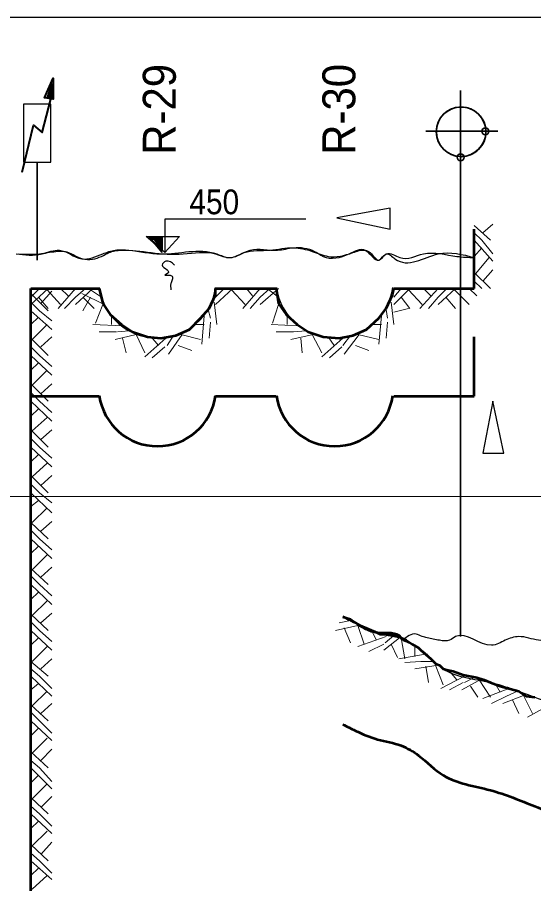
# Model space of a CAD drawing. Extents: x 8426.2 to 8495.4, y 19933.5 to 19963.2.
# Drawn here: x 8478.14 to 8482.31, y 19949.42 to 19956.41 of the extents above; entities that cross this region are included whole.
import ezdxf

# ---------------------------------------------------------------- set-up
doc = ezdxf.new("R2010")
doc.units = 0
doc.header["$LTSCALE"] = 0.11
doc.header["$PDMODE"] = 32
doc.header["$PDSIZE"] = 0.055
for name, color, linetype, lineweight in [('1', 7, 'Continuous', 35), ('2', 7, 'Continuous', 13), ('3', 7, 'Continuous', 25)]:
    doc.layers.add(name, color=color, linetype=linetype, lineweight=lineweight)

msp = doc.modelspace()

# ---------------------------------------------------------------- linework, layer by layer
at = {"layer": '1'}
for p, q in [((8481.72, 19955.08), (8481.72, 19955.82)), ((8481.44, 19955.49), (8482.01, 19955.49)), ((8481.45, 19955.49), (8482.02, 19955.49))]:
    msp.add_line(p, q, dxfattribs=at)
at = {"layer": '1', "lineweight": 40}
for points in [[(8478.43, 19955.75), (8478.36, 19955.76), (8478.43, 19955.92), (8478.43, 19955.75), (8478.42, 19955.76), (8478.42, 19955.87), (8478.38, 19955.76), (8478.42, 19955.76), (8478.42, 19955.82), (8478.39, 19955.77), (8478.41, 19955.77), (8478.42, 19955.8)], [(8478.18, 19955.16), (8478.27, 19955.54), (8478.34, 19955.48), (8478.41, 19955.75)]]:
    msp.add_lwpolyline(points, dxfattribs=at)
at = {"layer": '1'}
for points in [[(8481.72, 19951.41), (8481.72, 19953.26), (8481.72, 19955.82)], [(8481.92, 19955.49), (8481.72, 19955.49), (8481.72, 19955.69)], [(8481.52, 19955.49), (8481.72, 19955.49), (8481.72, 19955.28)], [(8479.31, 19954.51), (8479.21, 19954.63), (8479.31, 19954.63), (8479.31, 19954.53), (8479.22, 19954.62), (8479.3, 19954.62), (8479.3, 19954.55), (8479.25, 19954.61), (8479.29, 19954.61), (8479.3, 19954.56), (8479.28, 19954.61)], [(8479.29, 19954.58), (8479.28, 19954.61), (8479.27, 19954.61), (8479.3, 19954.56)]]:
    msp.add_lwpolyline(points, dxfattribs=at)
at = {"layer": '1', "lineweight": 25}
msp.add_lwpolyline([(8478.41, 19955.71), (8478.19, 19955.71), (8478.19, 19955.24), (8478.41, 19955.24)], close=True, dxfattribs=at)
msp.add_lwpolyline([(8480.47, 19954.78), (8479.33, 19954.78), (8479.33, 19954.51), (8479.18, 19954.64), (8479.45, 19954.64), (8479.33, 19954.51)], dxfattribs=at)
at = {"layer": '1'}
msp.add_circle((8481.7233, 19955.4865), 0.2004, dxfattribs=at)
for start, end in [(91.69169, 178.65388), (0.23992, 91.32093), (179.21012, 269.1404), (269.1404, 0.20975)]:
    msp.add_arc((8481.7245, 19955.4855), 0.2004, start, end, dxfattribs=at)
at = {"layer": '1', "lineweight": 25}
msp.add_spline([(8479.41, 19954.41), (8479.34, 19954.44), (8479.31, 19954.41), (8479.35, 19954.37), (8479.36, 19954.35), (8479.33, 19954.33), (8479.39, 19954.32), (8479.39, 19954.29), (8479.38, 19954.26), (8479.38, 19954.21)], degree=3, dxfattribs=at)
at = {"layer": '1'}
for p in [(8481.92, 19955.49), (8481.72, 19955.28)]:
    msp.add_point(p, dxfattribs=at)
at = {"layer": '2', "lineweight": 35}
msp.add_line((8478.3, 19955.24), (8478.3, 19954.45), dxfattribs=at)
at = {"layer": '2'}
for p, q in [((8481.83, 19954.73), (8481.96, 19954.61)), ((8481.9, 19954.67), (8481.98, 19954.74)), ((8481.83, 19954.67), (8481.89, 19954.61)), ((8481.83, 19954.61), (8481.98, 19954.44)), ((8481.89, 19954.61), (8481.98, 19954.5)), ((8481.83, 19954.48), (8481.89, 19954.55)), ((8481.84, 19954.34), (8481.95, 19954.47)), ((8481.9, 19954.28), (8481.98, 19954.37)), ((8481.83, 19954.35), (8481.96, 19954.22)), ((8478.32, 19954.22), (8478.25, 19954.15)), ((8478.39, 19954.22), (8478.25, 19954.09)), ((8478.61, 19954.22), (8478.47, 19954.06)), ((8478.49, 19954.22), (8478.55, 19954.16)), ((8478.69, 19954.22), (8478.61, 19954.15)), ((8478.75, 19954.22), (8478.61, 19954.09)), ((8479.81, 19954.22), (8479.74, 19954.15)), ((8479.88, 19954.22), (8479.74, 19954.09)), ((8480.1, 19954.22), (8479.96, 19954.06)), ((8479.99, 19954.22), (8480.04, 19954.16)), ((8480.18, 19954.22), (8480.1, 19954.15)), ((8480.25, 19954.22), (8480.1, 19954.09)), ((8481.24, 19954.22), (8481.18, 19954.15)), ((8481.31, 19954.22), (8481.18, 19954.09)), ((8481.54, 19954.22), (8481.39, 19954.06)), ((8481.42, 19954.22), (8481.48, 19954.16)), ((8481.61, 19954.22), (8481.54, 19954.15)), ((8481.68, 19954.22), (8481.54, 19954.09)), ((8481.79, 19954.22), (8481.85, 19954.16)), ((8481.83, 19954.28), (8481.89, 19954.22)), ((8478.25, 19954.18), (8478.39, 19954.04)), ((8478.31, 19954.15), (8478.39, 19954.06)), ((8478.33, 19954.1), (8478.42, 19954.2)), ((8478.38, 19954.21), (8478.49, 19954.09)), ((8478.61, 19954.15), (8478.52, 19954.06)), ((8478.84, 19954.09), (8478.66, 19954.18)), ((8478.73, 19954.15), (8478.67, 19954.04)), ((8478.67, 19954.15), (8478.76, 19954.06)), ((8478.82, 19954.15), (8478.73, 19954.21)), ((8479.87, 19954.21), (8479.98, 19954.09)), ((8480.1, 19954.15), (8480.02, 19954.06)), ((8480.25, 19954.15), (8480.17, 19954.21)), ((8481.24, 19954.15), (8481.31, 19954.06)), ((8481.3, 19954.21), (8481.41, 19954.09)), ((8481.54, 19954.15), (8481.46, 19954.06)), ((8481.6, 19954.15), (8481.68, 19954.06)), ((8481.67, 19954.21), (8481.79, 19954.09)), ((8478.25, 19954.11), (8478.32, 19954.04)), ((8478.83, 19954.09), (8478.77, 19953.94)), ((8479.73, 19954.11), (8479.75, 19953.93)), ((8480.25, 19954.09), (8480.2, 19953.94)), ((8481.16, 19954.11), (8481.18, 19953.93)), ((8478.25, 19954.04), (8478.42, 19953.89)), ((8478.32, 19954.04), (8478.42, 19953.96)), ((8479.68, 19954.05), (8479.7, 19953.98)), ((8481.12, 19954.05), (8481.13, 19953.98)), ((8481.18, 19954.03), (8481.3, 19954.06)), ((8478.25, 19953.93), (8478.31, 19953.99)), ((8478.9, 19954), (8478.9, 19953.93)), ((8479.65, 19954), (8479.63, 19953.77)), ((8479.7, 19953.95), (8479.69, 19953.82)), ((8480.32, 19954), (8480.32, 19953.93)), ((8481.08, 19954), (8481.06, 19953.77)), ((8481.13, 19953.95), (8481.12, 19953.82)), ((8478.26, 19953.81), (8478.38, 19953.93)), ((8478.99, 19953.92), (8478.75, 19953.93)), ((8478.94, 19953.87), (8478.8, 19953.87)), ((8479.04, 19953.88), (8478.95, 19953.87)), ((8479.57, 19953.93), (8479.65, 19953.93)), ((8480.41, 19953.92), (8480.19, 19953.93)), ((8480.37, 19953.87), (8480.23, 19953.87)), ((8480.47, 19953.88), (8480.37, 19953.87)), ((8481, 19953.93), (8481.08, 19953.93)), ((8478.25, 19953.82), (8478.39, 19953.68)), ((8478.33, 19953.75), (8478.42, 19953.83)), ((8479.1, 19953.85), (8478.93, 19953.81)), ((8478.99, 19953.82), (8479.02, 19953.7)), ((8479.1, 19953.85), (8479.17, 19953.7)), ((8479.34, 19953.82), (8479.17, 19953.67)), ((8479.22, 19953.83), (8479.28, 19953.76)), ((8479.4, 19953.84), (8479.35, 19953.76)), ((8479.47, 19953.85), (8479.36, 19953.69)), ((8479.46, 19953.85), (8479.62, 19953.81)), ((8480.53, 19953.85), (8480.35, 19953.81)), ((8480.43, 19953.82), (8480.44, 19953.7)), ((8480.52, 19953.85), (8480.6, 19953.7)), ((8480.77, 19953.82), (8480.6, 19953.67)), ((8480.65, 19953.83), (8480.7, 19953.76)), ((8480.83, 19953.84), (8480.77, 19953.76)), ((8480.9, 19953.85), (8480.78, 19953.69)), ((8480.89, 19953.85), (8481.06, 19953.81)), ((8478.25, 19953.75), (8478.32, 19953.68)), ((8479.33, 19953.75), (8479.23, 19953.66)), ((8479.44, 19953.76), (8479.55, 19953.72)), ((8480.76, 19953.75), (8480.66, 19953.66)), ((8480.87, 19953.76), (8480.98, 19953.72)), ((8478.25, 19953.68), (8478.42, 19953.52)), ((8478.32, 19953.68), (8478.42, 19953.59)), ((8478.25, 19953.56), (8478.31, 19953.62)), ((8478.26, 19953.44), (8478.38, 19953.56)), ((8478.25, 19953.45), (8478.39, 19953.31)), ((8478.33, 19953.37), (8478.42, 19953.45)), ((8478.25, 19953.38), (8478.32, 19953.31)), ((8478.25, 19953.31), (8478.42, 19953.15)), ((8478.32, 19953.31), (8478.42, 19953.22)), ((8478.25, 19953.19), (8478.31, 19953.25)), ((8478.26, 19953.07), (8478.38, 19953.18)), ((8478.25, 19953.08), (8478.39, 19952.94)), ((8478.33, 19953), (8478.42, 19953.08)), ((8478.25, 19953.01), (8478.32, 19952.94)), ((8478.25, 19952.94), (8478.42, 19952.78)), ((8478.32, 19952.94), (8478.42, 19952.85)), ((8478.25, 19952.82), (8478.31, 19952.88)), ((8478.26, 19952.7), (8478.38, 19952.81)), ((8478.25, 19952.71), (8478.39, 19952.57)), ((8478.33, 19952.63), (8478.42, 19952.71)), ((8478.25, 19952.64), (8478.32, 19952.57)), ((8478.25, 19952.57), (8478.42, 19952.41)), ((8478.32, 19952.57), (8478.42, 19952.49)), ((8478.25, 19952.46), (8478.31, 19952.51)), ((8478.26, 19952.33), (8478.38, 19952.45)), ((8478.25, 19952.33), (8478.39, 19952.2)), ((8478.33, 19952.26), (8478.42, 19952.34)), ((8478.25, 19952.27), (8478.32, 19952.2)), ((8478.25, 19952.2), (8478.42, 19952.04)), ((8478.32, 19952.2), (8478.42, 19952.11)), ((8478.25, 19952.08), (8478.31, 19952.14)), ((8478.26, 19951.95), (8478.38, 19952.07)), ((8478.25, 19951.96), (8478.39, 19951.83)), ((8478.33, 19951.89), (8478.42, 19951.97)), ((8478.25, 19951.9), (8478.32, 19951.83)), ((8478.25, 19951.83), (8478.42, 19951.67)), ((8478.25, 19951.71), (8478.31, 19951.77)), ((8478.32, 19951.83), (8478.42, 19951.74)), ((8478.26, 19951.58), (8478.38, 19951.7)), ((8478.25, 19951.59), (8478.39, 19951.46)), ((8478.33, 19951.52), (8478.42, 19951.6)), ((8478.25, 19951.53), (8478.32, 19951.46)), ((8480.89, 19951.5), (8480.71, 19951.46)), ((8480.83, 19951.54), (8480.74, 19951.52)), ((8480.89, 19951.5), (8480.94, 19951.35)), ((8478.25, 19951.46), (8478.42, 19951.3)), ((8478.32, 19951.46), (8478.42, 19951.37)), ((8480.78, 19951.48), (8480.83, 19951.36)), ((8481, 19951.46), (8481.04, 19951.38)), ((8481.18, 19951.42), (8481.11, 19951.36)), ((8478.25, 19951.34), (8478.31, 19951.4)), ((8481.12, 19951.41), (8480.89, 19951.33)), ((8481.1, 19951.35), (8480.98, 19951.29)), ((8481.24, 19951.41), (8481.1, 19951.3)), ((8481.16, 19951.35), (8481.21, 19951.24)), ((8481.24, 19951.4), (8481.27, 19951.23)), ((8478.26, 19951.21), (8478.38, 19951.33)), ((8481.35, 19951.34), (8481.35, 19951.25)), ((8478.25, 19951.21), (8478.39, 19951.09)), ((8478.33, 19951.15), (8478.42, 19951.23)), ((8481.45, 19951.27), (8481.22, 19951.23)), ((8481.4, 19951.21), (8481.27, 19951.2)), ((8481.5, 19951.21), (8481.4, 19951.21)), ((8478.25, 19951.15), (8478.32, 19951.09)), ((8481.54, 19951.18), (8481.35, 19951.15)), ((8481.44, 19951.17), (8481.46, 19951.04)), ((8481.52, 19951.17), (8481.58, 19951.02)), ((8478.25, 19951.09), (8478.42, 19950.93)), ((8478.32, 19951.09), (8478.42, 19950.99)), ((8481.75, 19951.09), (8481.56, 19950.99)), ((8481.63, 19951.13), (8481.69, 19951.06)), ((8481.89, 19951.07), (8481.73, 19950.98)), ((8481.83, 19951.08), (8481.75, 19951.04)), ((8478.25, 19950.98), (8478.31, 19951.03)), ((8481.74, 19951.04), (8481.63, 19950.98)), ((8481.8, 19951.01), (8481.86, 19950.92)), ((8481.87, 19951.06), (8481.96, 19950.92)), ((8482, 19951.03), (8482.04, 19950.96)), ((8478.26, 19950.85), (8478.38, 19950.97)), ((8482.11, 19950.99), (8481.9, 19950.91)), ((8482.09, 19950.93), (8481.97, 19950.87)), ((8482.24, 19950.94), (8482.06, 19950.87)), ((8482.18, 19950.97), (8482.09, 19950.93)), ((8482.23, 19950.93), (8482.3, 19950.79)), ((8478.25, 19950.86), (8478.39, 19950.73)), ((8478.33, 19950.79), (8478.42, 19950.87)), ((8482.14, 19950.9), (8482.19, 19950.79)), ((8482.46, 19950.87), (8482.26, 19950.76)), ((8478.25, 19950.8), (8478.32, 19950.73)), ((8478.25, 19950.73), (8478.42, 19950.57)), ((8478.32, 19950.73), (8478.42, 19950.63)), ((8478.25, 19950.61), (8478.31, 19950.67)), ((8478.26, 19950.47), (8478.38, 19950.59)), ((8478.25, 19950.48), (8478.39, 19950.35)), ((8478.33, 19950.41), (8478.42, 19950.5)), ((8478.25, 19950.41), (8478.32, 19950.35)), ((8478.25, 19950.35), (8478.42, 19950.18)), ((8478.32, 19950.35), (8478.42, 19950.24)), ((8478.25, 19950.23), (8478.31, 19950.29)), ((8478.26, 19950.1), (8478.38, 19950.22)), ((8478.25, 19950.11), (8478.39, 19949.98)), ((8478.33, 19950.03), (8478.42, 19950.12)), ((8478.25, 19950.04), (8478.32, 19949.98)), ((8478.25, 19949.98), (8478.42, 19949.82)), ((8478.32, 19949.98), (8478.42, 19949.88)), ((8478.25, 19949.86), (8478.31, 19949.92)), ((8478.26, 19949.72), (8478.38, 19949.84)), ((8478.33, 19949.65), (8478.42, 19949.75)), ((8478.25, 19949.73), (8478.39, 19949.6)), ((8478.25, 19949.66), (8478.32, 19949.6)), ((8478.25, 19949.6), (8478.42, 19949.45)), ((8478.25, 19949.48), (8478.31, 19949.54)), ((8478.32, 19949.6), (8478.42, 19949.5)), ((8478.26, 19949.37), (8478.38, 19949.48))]:
    msp.add_line(p, q, dxfattribs=at)
at = {"layer": '2', "lineweight": 53}
for p, q in [((8481.83, 19954.22), (8481.83, 19954.7)), ((8478.25, 19954.22), (8478.8, 19954.22)), ((8478.25, 19948.11), (8478.25, 19954.22)), ((8479.74, 19954.22), (8480.23, 19954.22)), ((8481.18, 19954.22), (8481.83, 19954.22)), ((8481.83, 19953.35), (8481.83, 19953.83)), ((8478.25, 19953.35), (8478.8, 19953.35)), ((8478.25, 19947.25), (8478.25, 19953.35)), ((8479.74, 19953.35), (8480.23, 19953.35)), ((8481.18, 19953.35), (8481.83, 19953.35))]:
    msp.add_line(p, q, dxfattribs=at)
at = {"layer": '2', "lineweight": 25}
for points in [[(8480.72, 19954.79), (8481.15, 19954.7), (8481.15, 19954.87)], [(8481.98, 19953.31), (8481.9, 19952.89), (8482.07, 19952.89)]]:
    msp.add_lwpolyline(points, close=True, dxfattribs=at)
at = {"layer": '2', "lineweight": 53}
for points in [[(8481.83, 19954.22), (8481.83, 19954.47), (8481.83, 19954.7)], [(8478.8, 19954.22), (8478.83, 19954.1), (8478.89, 19954.01), (8478.98, 19953.93), (8479.07, 19953.87), (8479.19, 19953.83), (8479.3, 19953.82), (8479.42, 19953.84), (8479.53, 19953.89), (8479.62, 19953.98), (8479.69, 19954.06), (8479.74, 19954.17), (8479.74, 19954.22)], [(8480.23, 19954.22), (8480.25, 19954.1), (8480.31, 19954.01), (8480.4, 19953.93), (8480.49, 19953.87), (8480.61, 19953.83), (8480.74, 19953.82), (8480.85, 19953.84), (8480.96, 19953.89), (8481.06, 19953.98), (8481.12, 19954.06), (8481.17, 19954.17), (8481.18, 19954.22)], [(8480.77, 19951.57), (8480.83, 19951.55), (8480.87, 19951.52), (8480.91, 19951.5), (8480.98, 19951.47), (8481.05, 19951.44), (8481.07, 19951.43), (8481.1, 19951.43), (8481.17, 19951.42), (8481.21, 19951.41), (8481.23, 19951.41), (8481.24, 19951.4), (8481.28, 19951.38), (8481.33, 19951.35), (8481.38, 19951.32), (8481.4, 19951.3), (8481.48, 19951.23), (8481.52, 19951.19), (8481.55, 19951.18), (8481.58, 19951.15), (8481.62, 19951.14), (8481.66, 19951.13), (8481.74, 19951.1), (8481.85, 19951.08), (8481.91, 19951.06), (8481.96, 19951.04), (8482.04, 19951.01), (8482.19, 19950.97), (8482.25, 19950.93), (8482.32, 19950.92)]]:
    msp.add_lwpolyline(points, dxfattribs=at)
for centre in [(8479.2716, 19953.4212), (8480.7023, 19953.4212)]:
    msp.add_arc(centre, 0.4743, 188.03456, 351.96544, dxfattribs=at)
for points in [[(8481.25, 19951.38), (8481.24, 19951.4), (8481.05, 19951.44), (8480.87, 19951.52), (8480.77, 19951.57)], [(8480.77, 19950.7), (8480.87, 19950.65), (8481.05, 19950.58), (8481.24, 19950.53), (8481.38, 19950.45), (8481.58, 19950.29), (8481.96, 19950.17), (8482.32, 19950.04), (8482.74, 19949.9), (8483.07, 19949.8), (8483.44, 19949.63), (8483.69, 19949.57), (8484.12, 19949.42), (8484.86, 19949.11)]]:
    msp.add_spline(points, degree=3, dxfattribs=at)
at = {"layer": '3'}
for p, q in [((8431.27, 19956.41), (8493.73, 19956.41)), ((8480.23, 19954.22), (8479.74, 19954.22)), ((8481.83, 19954.22), (8481.18, 19954.22))]:
    msp.add_line(p, q, dxfattribs=at)
at = {"layer": '3', "lineweight": 13}
msp.add_line((8431.27, 19952.54), (8493.73, 19952.54), dxfattribs=at)
at = {"layer": '3'}
msp.add_lwpolyline([(8478.8, 19954.22), (8478.25, 19954.22), (8478.25, 19948.11)], dxfattribs=at)
for centre in [(8479.2716, 19954.2939), (8480.7023, 19954.2939)]:
    msp.add_arc(centre, 0.4743, 188.03456, 351.96544, dxfattribs=at)
for points in [[(8478.13, 19954.5), (8478.34, 19954.5), (8478.48, 19954.53), (8478.66, 19954.46), (8478.83, 19954.5), (8478.93, 19954.53), (8479.04, 19954.53), (8479.3, 19954.5), (8479.75, 19954.5), (8479.85, 19954.47), (8480.02, 19954.53), (8480.24, 19954.53), (8480.37, 19954.55), (8480.54, 19954.52), (8480.61, 19954.48), (8480.82, 19954.5), (8480.95, 19954.53), (8481.06, 19954.45), (8481.12, 19954.5), (8481.19, 19954.46), (8481.54, 19954.5), (8481.83, 19954.47)], [(8478.15, 19954.5), (8478.32, 19954.5), (8478.45, 19954.52), (8478.52, 19954.52), (8478.67, 19954.46), (8478.82, 19954.48), (8478.88, 19954.51), (8478.98, 19954.53), (8479.22, 19954.51), (8479.48, 19954.5), (8479.74, 19954.5), (8479.86, 19954.47), (8479.97, 19954.51), (8480.18, 19954.53), (8480.37, 19954.55), (8480.52, 19954.52), (8480.65, 19954.48), (8480.85, 19954.51), (8480.95, 19954.53), (8480.99, 19954.51), (8481.06, 19954.45), (8481.12, 19954.5), (8481.23, 19954.47), (8481.42, 19954.5), (8481.69, 19954.48), (8481.83, 19954.47)], [(8484.92, 19951.44), (8484.8, 19951.47), (8484.71, 19951.47), (8484.59, 19951.41), (8484.47, 19951.47), (8484.35, 19951.43), (8484.19, 19951.43), (8484.09, 19951.44), (8483.83, 19951.41), (8483.63, 19951.41), (8483.56, 19951.44), (8483.41, 19951.4), (8483.14, 19951.38), (8483.03, 19951.38), (8482.93, 19951.38), (8482.69, 19951.32), (8482.62, 19951.36), (8482.49, 19951.38), (8482.35, 19951.38), (8482.19, 19951.41), (8482.08, 19951.38), (8481.97, 19951.34), (8481.68, 19951.41), (8481.63, 19951.38), (8481.55, 19951.38), (8481.45, 19951.4), (8481.41, 19951.41), (8481.36, 19951.43), (8481.25, 19951.38)], [(8484.92, 19951.44), (8484.8, 19951.47), (8484.71, 19951.47), (8484.59, 19951.41), (8484.47, 19951.47), (8484.35, 19951.43), (8484.19, 19951.43), (8484.09, 19951.44), (8483.83, 19951.41), (8483.63, 19951.41), (8483.56, 19951.44), (8483.41, 19951.4), (8483.14, 19951.38), (8483.03, 19951.38), (8482.93, 19951.38), (8482.69, 19951.32), (8482.62, 19951.36), (8482.49, 19951.38), (8482.35, 19951.38), (8482.19, 19951.41), (8482.08, 19951.38), (8481.97, 19951.34), (8481.68, 19951.41), (8481.63, 19951.38), (8481.55, 19951.38), (8481.45, 19951.4), (8481.41, 19951.41), (8481.36, 19951.43), (8481.25, 19951.38)], [(8481.25, 19951.38), (8481.38, 19951.32), (8481.58, 19951.15), (8481.96, 19951.04), (8482.32, 19950.92), (8482.74, 19950.79), (8483.07, 19950.68), (8483.44, 19950.51), (8483.69, 19950.45), (8484.12, 19950.28), (8484.86, 19949.99)]]:
    msp.add_spline(points, degree=3, dxfattribs=at)

# ---------------------------------------------------------------- texts
at = {"layer": '1', "width": 0.95}
for s, p in [('R-29', (8479.42, 19955.3)), ('R-30', (8480.87, 19955.3))]:
    msp.add_text(s, height=0.2665, rotation=90, dxfattribs=at).set_placement(p)
at = {"layer": '2', "width": 0.9}
msp.add_text('450', height=0.1999, dxfattribs=at).set_placement((8479.53, 19954.82))

doc.saveas('drawing.dxf')
